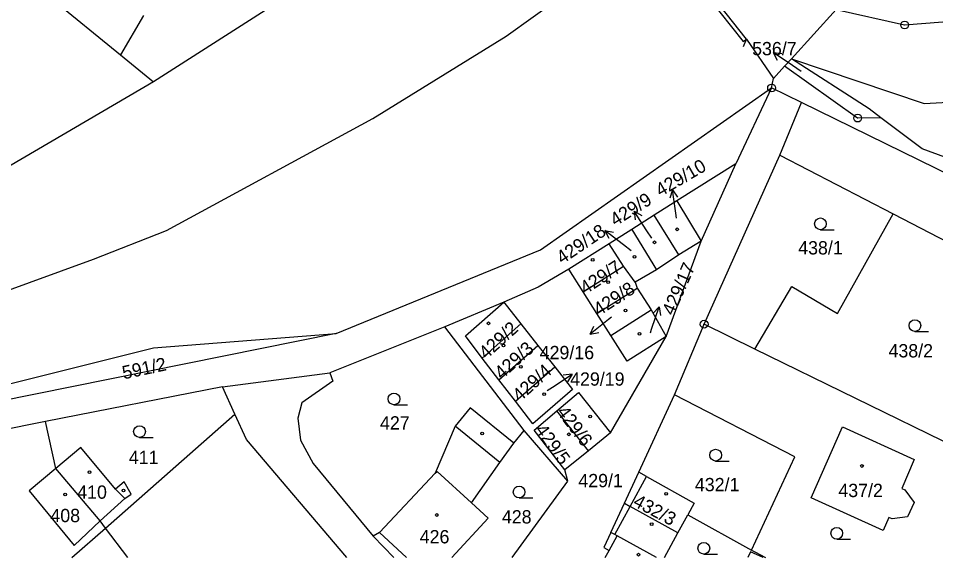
# Model space of a CAD drawing. Extents: x -776606 to -776076, y -974328 to -973875.
# Drawn here: x -776421.1 to -776303.9, y -974327.7 to -974258.8 of the extents above; entities that cross this region are included whole.
import ezdxf

# ---------------------------------------------------------------- set-up
doc = ezdxf.new("R2010")
doc.units = 0
for name, color, linetype in [('Hranice parcel', 7, 'Continuous'), ('Parcelní čísla', 7, 'Continuous'), ('Pop  PČ popisy', 7, 'Continuous'), ('Poz předměty', 7, 'Continuous'), ('Vnitřní kresba', 7, 'Continuous'), ('Značky bodu BP', 7, 'Continuous'), ('Značky budov', 7, 'Continuous'), ('Značky kultur', 7, 'Continuous')]:
    doc.layers.add(name, color=color, linetype=linetype)

msp = doc.modelspace()

# ---------------------------------------------------------------- linework, layer by layer
at = {"layer": 'Hranice parcel'}
for p, q in [((-776432.18, -974243.72), (-776408.09, -974263.43)), ((-776380.54, -974251.96), (-776403.84, -974266.91)), ((-776405.12, -974258.44), (-776408.09, -974263.43)), ((-776408.09, -974263.43), (-776403.84, -974266.91)), ((-776323.22, -974264.9), (-776322.34, -974263.94)), ((-776403.84, -974266.91), (-776431.78, -974283.23)), ((-776336.99, -974282.11), (-776339.88, -974283.93)), ((-776339.88, -974283.93), (-776342.75, -974285.75)), ((-776336.75, -974289), (-776339.88, -974283.93)), ((-776309.36, -974283.76), (-776299.93, -974288.65)), ((-776342.75, -974285.75), (-776345.62, -974287.57)), ((-776342.75, -974285.75), (-776339.6, -974290.9)), ((-776345.62, -974287.57), (-776350.78, -974290.83)), ((-776343.81, -974290.44), (-776345.62, -974287.57)), ((-776336.75, -974289), (-776339.6, -974290.9)), ((-776348.97, -974293.7), (-776343.81, -974290.44)), ((-776342.3, -974292.5), (-776343.81, -974290.44)), ((-776348.97, -974293.7), (-776350.78, -974290.83)), ((-776339.6, -974290.9), (-776342.3, -974292.5)), ((-776342.3, -974292.5), (-776342.04, -974293.23)), ((-776347.2, -974296.49), (-776348.97, -974293.7)), ((-776347.2, -974296.49), (-776342.04, -974293.23)), ((-776342.04, -974293.23), (-776340.28, -974296.02)), ((-776345.44, -974299.28), (-776340.28, -974296.02)), ((-776345.44, -974299.28), (-776347.2, -974296.49)), ((-776366.62, -974298.19), (-776381.33, -974304.06)), ((-776356.49, -974311.44), (-776366.62, -974298.19)), ((-776361.87, -974302.2), (-776356.9, -974297.82)), ((-776356.9, -974297.82), (-776354.73, -974300.57)), ((-776337.3, -974306.86), (-776333.5, -974297.85)), ((-776327.02, -974301.02), (-776333.5, -974297.85)), ((-776380.5, -974299.02), (-776464.24, -974315.93)), ((-776359.74, -974304.94), (-776354.73, -974300.57)), ((-776354.73, -974300.57), (-776352.57, -974303.31)), ((-776297.07, -974315.67), (-776327.02, -974301.02)), ((-776359.74, -974304.94), (-776361.87, -974302.2)), ((-776357.6, -974307.68), (-776352.57, -974303.31)), ((-776395.04, -974305.86), (-776381.33, -974304.06)), ((-776357.6, -974307.68), (-776359.74, -974304.94)), ((-776395.04, -974305.86), (-776417.64, -974310.29)), ((-776393.45, -974309.32), (-776395.04, -974305.86)), ((-776409.99, -974323.88), (-776393.45, -974309.32)), ((-776348.28, -974314.03), (-776352.31, -974308.92)), ((-776417.64, -974310.29), (-776425.93, -974311.95)), ((-776416.33, -974316.29), (-776417.64, -974310.29)), ((-776357.83, -974313.04), (-776356.49, -974311.44)), ((-776410.68, -974322.95), (-776416.33, -974316.29)), ((-776343.69, -974320.7), (-776342.94, -974321.12)), ((-776336.85, -974324.51), (-776342.94, -974321.12)), ((-776336.85, -974324.51), (-776335.58, -974322.18)), ((-776335.58, -974322.18), (-776327.45, -974326.69)), ((-776409.99, -974323.88), (-776410.68, -974322.95)), ((-776365.73, -974327.66), (-776361.1, -974322.64)), ((-776414.29, -974327.66), (-776409.99, -974323.88)), ((-776407.13, -974327.66), (-776409.99, -974323.88)), ((-776338.58, -974327.66), (-776336.85, -974324.51)), ((-776375.79, -974324.92), (-776373.13, -974327.66)), ((-776339.58, -974327.66), (-776344.62, -974324.87))]:
    msp.add_line(p, q, dxfattribs=at)
for points in [[(-776322.34, -974263.94), (-776316.64, -974257.67), (-776307.88, -974259.63), (-776300.82, -974259.07), (-776293.46, -974256.12), (-776281.91, -974242.23)], [(-776322.34, -974263.94), (-776305.38, -974269.65), (-776296.22, -974269.13), (-776284.45, -974265.69), (-776280.95, -974262.62)], [(-776310.94, -974271.48), (-776312.43, -974270.36), (-776322.34, -974263.94)], [(-776324.88, -974267.68), (-776324.63, -974266.46), (-776323.22, -974264.9)], [(-776310.94, -974271.48), (-776313.89, -974271.52), (-776323.22, -974264.9)], [(-776380.5, -974299.02), (-776354.39, -974288.37), (-776324.88, -974267.68)], [(-776324.88, -974267.68), (-776329.47, -974277.36), (-776336.99, -974282.11)], [(-776288.8, -974285.31), (-776321.08, -974269.54), (-776324.88, -974267.68)], [(-776287.02, -974280.17), (-776295.33, -974279.25), (-776305.65, -974275.44), (-776310.94, -974271.48)], [(-776333.5, -974297.85), (-776323.82, -974276.26), (-776309.36, -974283.76)], [(-776336.99, -974282.11), (-776333.86, -974287.23), (-776336.75, -974289)], [(-776327.02, -974301.02), (-776322.3, -974293.03), (-776316.46, -974296.49), (-776309.36, -974283.76)], [(-776350.78, -974290.83), (-776354.72, -974293.13), (-776359.09, -974295.04), (-776366.62, -974298.19)], [(-776361.87, -974302.2), (-776364, -974299.35), (-776359.09, -974295.04), (-776356.9, -974297.82)], [(-776340.28, -974296.02), (-776338.37, -974299.42), (-776343.35, -974302.58), (-776345.44, -974299.28)], [(-776464.24, -974315.93), (-776403.84, -974300.87), (-776380.5, -974299.02)], [(-776352.57, -974303.31), (-776350.3, -974306.18), (-776355.38, -974310.58), (-776357.6, -974307.68)], [(-776381.33, -974304.06), (-776380.93, -974305.13), (-776384.89, -974307.87), (-776385.42, -974309.83), (-776385.09, -974312.64), (-776383.44, -974315.62), (-776375.79, -974324.92)], [(-776352.31, -974308.92), (-776349.57, -974306.58), (-776345.45, -974311.72), (-776348.28, -974314.03)], [(-776343.69, -974320.7), (-776341.86, -974316.73), (-776337.3, -974306.86)], [(-776327.45, -974326.69), (-776321.89, -974314.77), (-776337.3, -974306.86)], [(-776379.16, -974327.66), (-776391.97, -974312.58), (-776393.45, -974309.32)], [(-776357.83, -974313.04), (-776363.4, -974308.53), (-776365.3, -974310.86), (-776367.86, -974316.89), (-776374.96, -974324.46), (-776375.79, -974324.92)], [(-776348.28, -974314.03), (-776351.28, -974316.46), (-776355.2, -974311.38), (-776352.31, -974308.92)], [(-776358.01, -974327.66), (-776350.91, -974317.88), (-776356.49, -974311.44)], [(-776309.88, -974322.53), (-776310.64, -974324.19), (-776319.84, -974320.01), (-776315.83, -974310.94), (-776306.65, -974315.14), (-776308.25, -974318.84), (-776307.86, -974319.01), (-776306.66, -974320.63), (-776307.5, -974322.47), (-776309.47, -974322.71), (-776309.88, -974322.53)], [(-776410.68, -974322.95), (-776407.51, -974320.1), (-776406.7, -974319.57), (-776407.6, -974318), (-776408.7, -974318.9), (-776413.15, -974313.59), (-776416.33, -974316.29)], [(-776361.1, -974322.64), (-776363.24, -974320.67), (-776359.6, -974315.52), (-776357.83, -974313.04)], [(-776342.94, -974321.12), (-776340.87, -974317.29), (-776334.78, -974320.71), (-776335.58, -974322.18)], [(-776344.62, -974324.87), (-776344.9, -974324.72), (-776345.42, -974324.44), (-776343.69, -974320.7)], [(-776346.14, -974327.66), (-776345.63, -974326.73), (-776344.62, -974324.87)], [(-776325.97, -974327.66), (-776327.56, -974326.94), (-776327.91, -974327.66)], [(-776327.45, -974326.69), (-776326.94, -974326.97), (-776325.66, -974327.66)]]:
    msp.add_lwpolyline(points, dxfattribs=at)
at = {"layer": 'Pop  PČ popisy'}
for p, q in [((-776322.21, -974264.81), (-776324.7, -974263.13)), ((-776324.7, -974263.13), (-776323.59, -974263.28)), ((-776324.7, -974263.13), (-776324.15, -974264.11)), ((-776321.11, -974265.57), (-776322.21, -974264.81)), ((-776337.55, -974280.7), (-776337.9, -974281.76)), ((-776337.13, -974283.67), (-776337.55, -974280.7)), ((-776337.55, -974280.7), (-776336.91, -974281.62)), ((-776340.81, -974285.91), (-776342.44, -974283.39)), ((-776342.44, -974283.39), (-776341.48, -974283.96)), ((-776342.44, -974283.39), (-776342.32, -974284.51)), ((-776337.04, -974284.31), (-776337.13, -974283.67)), ((-776343.81, -974287.72), (-776346.18, -974285.87)), ((-776346.18, -974285.87), (-776345.08, -974286.09)), ((-776346.18, -974285.87), (-776345.69, -974286.88)), ((-776340.19, -974286.86), (-776340.81, -974285.91)), ((-776342.82, -974288.48), (-776343.81, -974287.72)), ((-776340.21, -974298.47), (-776339.23, -974295.63)), ((-776339.23, -974295.63), (-776340.03, -974296.42)), ((-776339.23, -974295.63), (-776339.09, -974296.74)), ((-776345.71, -974297.24), (-776348.04, -974299.13)), ((-776345.35, -974296.95), (-776345.71, -974297.24)), ((-776348.04, -974299.13), (-776347.58, -974298.11)), ((-776340.37, -974298.93), (-776340.21, -974298.47)), ((-776348.04, -974299.13), (-776346.95, -974298.89)), ((-776352.89, -974305.87), (-776350.37, -974304.24)), ((-776350.37, -974304.24), (-776351.49, -974304.36)), ((-776350.37, -974304.24), (-776350.94, -974305.2)), ((-776353.54, -974306.3), (-776352.89, -974305.87))]:
    msp.add_line(p, q, dxfattribs=at)
at = {"layer": 'Poz předměty'}
for p, q in [((-776358.8, -974261.05), (-776342.73, -974249.52)), ((-776375.83, -974271.58), (-776358.8, -974261.05)), ((-776402.2, -974285.89), (-776375.83, -974271.58)), ((-776411.53, -974289.53), (-776402.2, -974285.89)), ((-776449.01, -974303.15), (-776411.53, -974289.53))]:
    msp.add_line(p, q, dxfattribs=at)
at = {"layer": 'Vnitřní kresba'}
for p, q in [((-776346, -974239.7), (-776328.51, -974261.74)), ((-776328.07, -974261.46), (-776345.5, -974239.35)), ((-776328.51, -974261.74), (-776328.07, -974261.46)), ((-776328.48, -974262.37), (-776328.07, -974261.46)), ((-776328.07, -974261.46), (-776324.63, -974266.46)), ((-776323.82, -974276.26), (-776321.08, -974269.54)), ((-776333.86, -974287.23), (-776329.47, -974277.36)), ((-776338.37, -974299.42), (-776333.86, -974287.23)), ((-776345.45, -974311.72), (-776338.37, -974299.42)), ((-776359.6, -974315.52), (-776365.3, -974310.86)), ((-776416.33, -974316.29), (-776419.74, -974319.14)), ((-776367.86, -974316.89), (-776367.62, -974316.64)), ((-776367.62, -974316.64), (-776363.24, -974320.67)), ((-776350.91, -974317.88), (-776351.28, -974316.46)), ((-776340.87, -974317.29), (-776341.86, -974316.73)), ((-776419.74, -974319.14), (-776414, -974326.1)), ((-776408.7, -974318.9), (-776407.51, -974320.1)), ((-776344.9, -974324.72), (-776342.94, -974321.12)), ((-776414, -974326.1), (-776410.68, -974322.95)), ((-776374.96, -974324.46), (-776371.54, -974327.66)), ((-776345.42, -974324.44), (-776346.3, -974326.35)), ((-776346.3, -974326.35), (-776345.63, -974326.73))]:
    msp.add_line(p, q, dxfattribs=at)
at = {"layer": 'Značky bodu BP'}
for centre, radius in [((-776307.88, -974259.63), 0.5), ((-776307.88, -974259.63), 0.0303), ((-776324.88, -974267.68), 0.5), ((-776324.88, -974267.68), 0.0303), ((-776313.89, -974271.52), 0.5), ((-776313.89, -974271.52), 0.0303), ((-776333.5, -974297.85), 0.5), ((-776333.5, -974297.85), 0.0303)]:
    msp.add_circle(centre, radius, dxfattribs=at)
at = {"layer": 'Značky budov'}
for centre in [(-776336.93, -974285.73), (-776339.84, -974287.39), (-776342.4, -974289.25), (-776347.74, -974289.64), (-776345.77, -974292.47), (-776343.53, -974296.1), (-776361.04, -974297.74), (-776341.76, -974299.07), (-776359.15, -974300.56), (-776356.93, -974303.3), (-776353.95, -974306.8), (-776348.05, -974309.63), (-776361.85, -974311.8), (-776350.78, -974311.91), (-776313.33, -974315.96), (-776412.04, -974316.74), (-776415.13, -974319.61), (-776407.68, -974319.08), (-776338.36, -974319.52), (-776367.66, -974322.22), (-776340.2, -974323.38), (-776341.89, -974327.28)]:
    msp.add_circle(centre, 0.175, dxfattribs=at)
at = {"layer": 'Značky kultur'}
for p, q in [((-776318.64, -974285.78), (-776316.89, -974285.78)), ((-776306.57, -974298.77), (-776304.82, -974298.77)), ((-776373.13, -974308.14), (-776371.38, -974308.14)), ((-776405.64, -974312.31), (-776403.89, -974312.31)), ((-776332.03, -974315.32), (-776330.28, -974315.32)), ((-776357.14, -974320.03), (-776355.39, -974320.03)), ((-776316.55, -974325.3), (-776314.8, -974325.3)), ((-776333.54, -974327.21), (-776331.79, -974327.21))]:
    msp.add_line(p, q, dxfattribs=at)
for centre in [(-776318.64, -974285.03), (-776306.57, -974298.02), (-776373.13, -974307.39), (-776405.64, -974311.56), (-776332.03, -974314.57), (-776357.14, -974319.28), (-776316.55, -974324.55), (-776333.54, -974326.46)]:
    msp.add_circle(centre, 0.75, dxfattribs=at)

# ---------------------------------------------------------------- texts
at = {"layer": 'Parcelní čísla'}
for s, p in [('536/7', (-776327.37, -974263.5)), ('438/1', (-776321.48, -974288.94)), ('429/16', (-776354.51, -974302.32)), ('438/2', (-776309.94, -974302.09)), ('429/19', (-776350.62, -974305.7)), ('427', (-776374.91, -974311.3)), ('411', (-776407.01, -974315.71)), ('429/1', (-776349.57, -974318.67)), ('432/1', (-776334.68, -974319.18)), ('410', (-776413.6, -974320.14)), ('437/2', (-776316.35, -974319.93)), ('408', (-776417.03, -974323.13)), ('428', (-776359.34, -974323.3)), ('426', (-776369.84, -974325.84))]:
    msp.add_text(s, height=1.7, dxfattribs=at).set_placement(p)
for s, rotation, p in [('429/10', 30, (-776339.09, -974281.61)), ('429/9', 32, (-776344.84, -974285.4)), ('429/18', 34, (-776351.64, -974290.24)), ('429/7', 33, (-776348.67, -974294.1)), ('429/17', 66, (-776337.41, -974296.84)), ('429/8', 33, (-776346.95, -974296.85)), ('429/2', 42, (-776361.35, -974302.42)), ('429/3', 42, (-776359.35, -974304.99)), ('591/2', 12, (-776407.66, -974304.9)), ('429/4', 42, (-776357.06, -974307.86)), ('429/6', 307, (-776352.42, -974309.07)), ('429/5', 306, (-776355.19, -974311.36)), ('432/3', 332, (-776342.7, -974320.98))]:
    msp.add_text(s, height=1.7, rotation=rotation, dxfattribs=at).set_placement(p)

doc.saveas('drawing.dxf')
